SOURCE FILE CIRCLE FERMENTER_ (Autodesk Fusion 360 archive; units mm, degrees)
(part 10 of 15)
sketch "Schizzo3" plane through (-153.8, 0, 0) normal (-1, 0, 0) x axis (0, -1, 0)
  line L1 (78.45, -61) -> (81.95, -61)
  line L2 (10.25, -63.8607) -> (10.25, -61)
  line L3 (-10.25, -63.8607) -> (10.25, -63.8607)
  line L4 (-10.25, -61) -> (-10.25, -63.8607)
  line L5 (10.25, -61) -> (-10.25, -61)
  line L6 (-81.95, -61) -> (-78.45, -61)
  line L7 (-20, -52.5) -> (20, -52.5)
  line L8 (20, -27.5) -> (-20, -27.5)
  line L9 (83.1107, -5.4967) -> (83.1107, -63.5)
  line L10 (83.1107, 16.5) -> (83.1107, -1.5033)
  curve K1 (65, 34.6107) -> (83.1107, 16.5)
  line L11 (-65, 34.6107) -> (65, 34.6107)
  curve K2 (-83.1107, 16.5) -> (-65, 34.6107)
  line L12 (-83.1107, -1.5033) -> (-83.1107, 16.5)
  line L13 (-83.1107, -63.5) -> (-83.1107, -5.4967)
  curve K3 (-65, -81.6107) -> (-83.1107, -63.5)
  line L14 (65, -81.6107) -> (-65, -81.6107)
  curve K4 (83.1107, -63.5) -> (65, -81.6107)
  line L15 (0, -13.1465) -> (0, 0)
  line L16 (-83.1107, -21.5033) -> (-83.1107, -25.4967)
  line L17 (83.1107, -21.5033) -> (83.1107, -25.4967)
  curve K5 (83.1107, 20.6888) -> (83.1107, 16.5)
  curve K6 (83.0385, 23.5828) -> (83.1107, 20.6888)
  curve K7 (82.3781, 26.1138) -> (83.0385, 23.5828)
  curve K8 (82.0194, 27.4886) -> (82.3781, 26.1138)
  curve K9 (81.4495, 28.9265) -> (82.0194, 27.4886)
  curve K10 (80.4921, 30.2006) -> (81.4495, 28.9265)
  curve K11 (79.931, 30.9471) -> (80.4921, 30.2006)
  curve K12 (79.1144, 31.8115) -> (79.931, 30.9471)
  curve K13 (77.8234, 32.5796) -> (79.1144, 31.8115)
  curve K14 (76.3023, 33.4846) -> (77.8234, 32.5796)
  curve K15 (74.7016, 33.8962) -> (76.3023, 33.4846)
  curve K16 (73.5973, 34.1073) -> (74.7016, 33.8962)
  curve K17 (70.9971, 34.6043) -> (73.5973, 34.1073)
  curve K18 (67.9011, 34.6107) -> (70.9971, 34.6043)
  curve K19 (65, 34.6107) -> (67.9011, 34.6107)
  curve K20 (-68.2903, 34.6107) -> (-65, 34.6107)
  curve K21 (-71.7747, 34.5997) -> (-68.2903, 34.6107)
  curve K22 (-74.5519, 33.8966) -> (-71.7747, 34.5997)
  curve K23 (-76.1521, 33.4915) -> (-74.5519, 33.8966)
  curve K24 (-77.5147, 32.8746) -> (-76.1521, 33.4915)
  curve K25 (-78.6589, 32.0231) -> (-77.5147, 32.8746)
  curve K26 (-79.6443, 31.2898) -> (-78.6589, 32.0231)
  curve K27 (-80.4322, 30.4068) -> (-79.6443, 31.2898)
  curve K28 (-81.065, 29.3452) -> (-80.4322, 30.4068)
  curve K29 (-81.8269, 28.067) -> (-81.065, 29.3452)
  curve K30 (-82.3123, 26.6067) -> (-81.8269, 28.067)
  curve K31 (-82.6049, 25.1185) -> (-82.3123, 26.6067)
  curve K32 (-83.0566, 22.8211) -> (-82.6049, 25.1185)
  curve K33 (-83.1107, 20.1337) -> (-83.0566, 22.8211)
  curve K34 (-83.1107, 16.5) -> (-83.1107, 20.1337)
  curve K35 (-83.1107, -67.6888) -> (-83.1107, -63.5)
  curve K36 (-83.0385, -70.5828) -> (-83.1107, -67.6888)
  curve K37 (-82.3781, -73.1138) -> (-83.0385, -70.5828)
  curve K38 (-82.0194, -74.4886) -> (-82.3781, -73.1138)
  curve K39 (-81.4495, -75.9266) -> (-82.0194, -74.4886)
  curve K40 (-80.4921, -77.2006) -> (-81.4495, -75.9266)
  curve K41 (-79.931, -77.9471) -> (-80.4921, -77.2006)
  curve K42 (-79.1144, -78.8115) -> (-79.931, -77.9471)
  curve K43 (-77.8234, -79.5796) -> (-79.1144, -78.8115)
  curve K44 (-76.3023, -80.4846) -> (-77.8234, -79.5796)
  curve K45 (-74.7016, -80.8963) -> (-76.3023, -80.4846)
  curve K46 (-73.5973, -81.1073) -> (-74.7016, -80.8963)
  curve K47 (-70.9971, -81.6043) -> (-73.5973, -81.1073)
  curve K48 (-67.9011, -81.6107) -> (-70.9971, -81.6043)
  curve K49 (-65, -81.6107) -> (-67.9011, -81.6107)
  curve K50 (68.2903, -81.6107) -> (65, -81.6107)
  curve K51 (71.7747, -81.5997) -> (68.2903, -81.6107)
  curve K52 (74.5519, -80.8966) -> (71.7747, -81.5997)
  curve K53 (76.1521, -80.4915) -> (74.5519, -80.8966)
  curve K54 (77.5147, -79.8746) -> (76.1521, -80.4915)
  curve K55 (78.6589, -79.0231) -> (77.5147, -79.8746)
  curve K56 (79.6443, -78.2898) -> (78.6589, -79.0231)
  curve K57 (80.4322, -77.4068) -> (79.6443, -78.2898)
  curve K58 (81.065, -76.3452) -> (80.4322, -77.4068)
  curve K59 (81.8269, -75.067) -> (81.065, -76.3452)
  curve K60 (82.3123, -73.6067) -> (81.8269, -75.067)
  curve K61 (82.6049, -72.1185) -> (82.3123, -73.6067)
  curve K62 (83.0566, -69.8211) -> (82.6049, -72.1185)
  curve K63 (83.1107, -67.1337) -> (83.0566, -69.8211)
  curve K64 (83.1107, -63.5) -> (83.1107, -67.1337)
  line L18 (78.45, -61) -> (81.95, -61)
  line L19 (10.25, -63.8607) -> (10.25, -61)
  line L20 (-10.25, -63.8607) -> (10.25, -63.8607)
  line L21 (-10.25, -61) -> (-10.25, -63.8607)
  line L22 (-81.95, -61) -> (-78.45, -61)
  line L23 (-20, -52.5) -> (20, -52.5)
  line L24 (20, -27.5) -> (-20, -27.5)
  line L25 (83.1107, -5.4967) -> (83.1107, -63.5)
  line L26 (83.1107, 16.5) -> (83.1107, -1.5033)
  curve K65 (65, 34.6107) -> (83.1107, 16.5)
  line L27 (-65, 34.6107) -> (65, 34.6107)
  curve K66 (-83.1107, 16.5) -> (-65, 34.6107)
  line L28 (-83.1107, -1.5033) -> (-83.1107, 16.5)
  line L29 (-83.1107, -63.5) -> (-83.1107, -5.4967)
  curve K67 (-65, -81.6107) -> (-83.1107, -63.5)
  line L30 (65, -81.6107) -> (-65, -81.6107)
  curve K68 (83.1107, -63.5) -> (65, -81.6107)
  line L31 (10.25, -61) -> (-10.25, -61)
  arc A1 centre (80.2, -61) radius 1.75 clockwise from (78.45, -61) to (81.95, -61)
  arc A2 centre (-80.2, -61) radius 1.75 clockwise from (-81.95, -61) to (-78.45, -61)
  arc A3 centre (-20, -40) radius 12.5 clockwise from (-20, -52.5) to (-20, -27.5)
  arc A4 centre (20, -40) radius 12.5 clockwise from (20, -27.5) to (20, -52.5)
  circle C1 centre (44.1, 31.7) radius 1.75
  circle C2 centre (-44.1, 31.7) radius 1.75
  circle C3 centre (0, 31.7) radius 1.75
  arc A5 centre (82.6107, -5.4967) radius 0.5 clockwise from (82.3802, -5.053) to (83.1107, -5.4967)
  arc A6 centre (81.5735, -3.5) radius 1.75 clockwise from (82.3802, -5.053) to (82.3802, -1.947)
  arc A7 centre (82.6107, -1.5033) radius 0.5 clockwise from (83.1107, -1.5033) to (82.3802, -1.947)
  arc A8 centre (-82.6107, -1.5033) radius 0.5 clockwise from (-82.3802, -1.947) to (-83.1107, -1.5033)
  arc A9 centre (-81.5735, -3.5) radius 1.75 clockwise from (-82.3802, -1.947) to (-82.3802, -5.053)
  arc A10 centre (-82.6107, -5.4967) radius 0.5 clockwise from (-83.1107, -5.4967) to (-82.3802, -5.053)
  circle C4 centre (44.1, -78.7) radius 1.75
  circle C5 centre (-44.1, -78.7) radius 1.75
  circle C6 centre (0, -78.7) radius 1.75
  arc A11 centre (-82.6107, -25.4967) radius 0.5 clockwise from (-83.1107, -25.4967) to (-82.3802, -25.053)
  arc A12 centre (-81.5735, -23.5) radius 1.75 clockwise from (-82.3802, -21.947) to (-82.3802, -25.053)
  arc A13 centre (-82.6107, -21.5033) radius 0.5 clockwise from (-82.3802, -21.947) to (-83.1107, -21.5033)
  arc A14 centre (81.5735, -23.5) radius 1.75 clockwise from (82.3802, -25.053) to (82.3802, -21.947)
  arc A15 centre (82.6107, -21.5033) radius 0.5 clockwise from (83.1107, -21.5033) to (82.3802, -21.947)
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  point P1 (0, 0)
  point P54 (0, 0)
  point P46 (-82.3802, -25.053)
  point P57 (82.3802, -25.053)
  point P47 (-83.1107, -25.4967)
  point P63 (83.1107, -25.4967)
  point P49 (-82.3802, -21.947)
  point P59 (82.3802, -21.947)
  point P51 (-82.3802, -21.947)
  point P61 (82.3802, -21.947)
  point P52 (-83.1107, -21.5033)
  point P60 (83.1107, -21.5033)
  coincident P1 P54
  vertical L15
  tangent A11 L16
  symmetric P46 L15 P57
  symmetric P47 L15 P63
  symmetric P49 L15 P59
  symmetric A12 L15 A14
  symmetric P51 L15 P61
  symmetric P52 L15 P60
  symmetric A13 L15 A15
extrude "Estrusione5" add sketch "Schizzo3" profile of L1 A1 L2 L3 L4 L5 L6 A2 L7 A3 L8 A4 against normal blind 3
extrude "Estrusione6" cut sketch "Schizzo3" against normal blind 3
sketch "Schizzo4" plane through (-153.8, 0, 0) normal (-1, 0, 0) x axis (0, -1, 0)
  line L1 (-83.1107, -63.5) -> (-83.1107, -25.4967)
  curve K1 (-65, -81.6107) -> (-83.1107, -63.5)
  line L2 (65, -81.6107) -> (-65, -81.6107)
  curve K2 (83.1107, -63.5) -> (65, -81.6107)
  line L3 (83.1107, -25.4967) -> (83.1107, -63.5)
  line L4 (83.1107, -5.4967) -> (83.1107, -21.5033)
  line L5 (83.1107, 16.5) -> (83.1107, -1.5033)
  curve K3 (65, 34.6107) -> (83.1107, 16.5)
  line L6 (-65, 34.6107) -> (65, 34.6107)
  curve K4 (-83.1107, 16.5) -> (-65, 34.6107)
  line L7 (-83.1107, -1.5033) -> (-83.1107, 16.5)
  line L8 (-83.1107, -21.5033) -> (-83.1107, -5.4967)
  line L9 (-83.1107, -1.5033) -> (-83.1107, -5.4967)
  line L10 (83.1107, -5.4967) -> (83.1107, -1.5033)
  arc A1 centre (-82.6107, -25.4967) radius 0.5 clockwise from (-83.1107, -25.4967) to (-82.3802, -25.053)
  arc A2 centre (82.6107, -25.4967) radius 0.5 clockwise from (82.3802, -25.053) to (83.1107, -25.4967)
  arc A3 centre (81.5735, -23.5) radius 1.75 clockwise from (82.3802, -25.053) to (82.3802, -21.947)
  arc A4 centre (82.6107, -21.5033) radius 0.5 clockwise from (83.1107, -21.5033) to (82.3802, -21.947)
  arc A5 centre (82.6107, -5.4967) radius 0.5 clockwise from (82.3802, -5.053) to (83.1107, -5.4967)
  arc A6 centre (81.5735, -3.5) radius 1.75 clockwise from (82.3802, -5.053) to (82.3802, -1.947)
  arc A7 centre (82.6107, -1.5033) radius 0.5 clockwise from (83.1107, -1.5033) to (82.3802, -1.947)
  arc A8 centre (-82.6107, -1.5033) radius 0.5 clockwise from (-82.3802, -1.947) to (-83.1107, -1.5033)
  arc A9 centre (-81.5735, -3.5) radius 1.75 clockwise from (-82.3802, -1.947) to (-82.3802, -5.053)
  arc A10 centre (-82.6107, -5.4967) radius 0.5 clockwise from (-83.1107, -5.4967) to (-82.3802, -5.053)
  arc A11 centre (-82.6107, -21.5033) radius 0.5 clockwise from (-82.3802, -21.947) to (-83.1107, -21.5033)
  arc A12 centre (-81.5735, -23.5) radius 1.75 clockwise from (-82.3802, -21.947) to (-82.3802, -25.053)
  circle C1 centre (-44.1, 31.7) radius 1.75
  circle C2 centre (-44.1, -78.7) radius 1.75
  circle C3 centre (44.1, 31.7) radius 1.75
  circle C4 centre (0, 31.7) radius 1.75
  circle C5 centre (44.1, -78.7) radius 1.75
  circle C6 centre (0, -78.7) radius 1.75
  point P32 (-83.1107, -5.4967)
  point P40 (-83.1107, -5.4967)
  point P27 (-83.1107, -1.5033)
  point P41 (-83.1107, -1.5033)
  point P21 (83.1107, -1.5033)
  point P42 (83.1107, -1.5033)
  point P16 (83.1107, -5.4967)
  point P43 (83.1107, -5.4967)
  coincident P32 P40
  coincident P27 P41
  coincident P21 P42
  coincident P16 P43
extrude "Estrusione7" add sketch "Schizzo4" profile of A5 A6 A7 A8 A9 A10 L9 L10 against normal blind 3
sketch "Schizzo5" plane through (-153.8, 0, 0) normal (-1, 0, 0) x axis (0, -1, 0)
  line L1 (-83.1107, -63.5) -> (-83.1107, -25.4967)
  curve K1 (-65, -81.6107) -> (-83.1107, -63.5)
  line L2 (65, -81.6107) -> (-65, -81.6107)
  curve K2 (83.1107, -63.5) -> (65, -81.6107)
  line L3 (83.1107, -25.4967) -> (83.1107, -63.5)
  line L4 (83.1107, 16.5) -> (83.1107, -21.5033)
  curve K3 (65, 34.6107) -> (83.1107, 16.5)
  line L5 (-65, 34.6107) -> (65, 34.6107)
  curve K4 (-83.1107, 16.5) -> (-65, 34.6107)
  line L6 (-83.1107, -21.5033) -> (-83.1107, 16.5)
  line L7 (-79.8235, -23.5) -> (79.8235, -23.5)
  arc A1 centre (-82.6107, -25.4967) radius 0.5 clockwise from (-83.1107, -25.4967) to (-82.3802, -25.053)
  arc A2 centre (82.6107, -25.4967) radius 0.5 clockwise from (82.3802, -25.053) to (83.1107, -25.4967)
  arc A3 centre (81.5735, -23.5) radius 1.75 clockwise from (82.3802, -25.053) to (82.3802, -21.947)
  arc A4 centre (82.6107, -21.5033) radius 0.5 clockwise from (83.1107, -21.5033) to (82.3802, -21.947)
  arc A5 centre (-82.6107, -21.5033) radius 0.5 clockwise from (-82.3802, -21.947) to (-83.1107, -21.5033)
  arc A6 centre (-81.5735, -23.5) radius 1.75 clockwise from (-82.3802, -21.947) to (-82.3802, -25.053)
  circle C1 centre (-44.1, 31.7) radius 1.75
  circle C2 centre (-44.1, -78.7) radius 1.75
  circle C3 centre (44.1, 31.7) radius 1.75
  circle C4 centre (0, 31.7) radius 1.75
  circle C5 centre (44.1, -78.7) radius 1.75
  circle C6 centre (0, -78.7) radius 1.75
  point P26 (79.8235, -23.5)
  point P27 (-79.8235, -23.5)
  point P28 (0, -23.5)
  midpoint A3 P26
  midpoint A6 P27
  midpoint L7 P28
component_insert "Inserimento componente3"
joint "Assembla5" alignAngle 0 alignOffsetX 0 alignOffsetY 0 alignOffsetZ 0
sketch "Schizzo10" plane through (-153.8, 0, 0) normal (-1, 0, 0) x axis (0, -1, 0)
  line L1 (-83.1107, -63.5) -> (-83.1107, -25.4967)
  curve K1 (-65, -81.6107) -> (-83.1107, -63.5)
  line L2 (65, -81.6107) -> (-65, -81.6107)
  curve K2 (83.1107, -63.5) -> (65, -81.6107)
  line L3 (83.1107, -25.4967) -> (83.1107, -63.5)
  line L4 (83.1107, 16.5) -> (83.1107, -21.5033)
  curve K3 (65, 34.6107) -> (83.1107, 16.5)
  line L5 (-65, 34.6107) -> (65, 34.6107)
  curve K4 (-83.1107, 16.5) -> (-65, 34.6107)
  line L6 (-83.1107, -21.5033) -> (-83.1107, 16.5)
  arc A1 centre (-82.6107, -25.4967) radius 0.5 clockwise from (-83.1107, -25.4967) to (-82.3802, -25.053)
  arc A2 centre (82.6107, -25.4967) radius 0.5 clockwise from (82.3802, -25.053) to (83.1107, -25.4967)
  arc A3 centre (81.5735, -23.5) radius 1.75 clockwise from (82.3802, -25.053) to (82.3802, -21.947)
  arc A4 centre (82.6107, -21.5033) radius 0.5 clockwise from (83.1107, -21.5033) to (82.3802, -21.947)
  arc A5 centre (-82.6107, -21.5033) radius 0.5 clockwise from (-82.3802, -21.947) to (-83.1107, -21.5033)
  arc A6 centre (-81.5735, -23.5) radius 1.75 clockwise from (-82.3802, -21.947) to (-82.3802, -25.053)
  circle C1 centre (-44.1, 31.7) radius 1.75
  circle C2 centre (-44.1, -78.7) radius 1.75
  circle C3 centre (-23, -23.5) radius 19.5
  arc A7 centre (21, -23.5) radius 12.5 clockwise from (10.7587, -30.667) to (10.7587, -16.3331)
  circle C4 centre (21, -23.5) radius 12.5
  circle C5 centre (44.1, 31.7) radius 1.75
  circle C6 centre (0, 31.7) radius 1.75
  circle C7 centre (44.1, -78.7) radius 1.75
  circle C8 centre (0, -78.7) radius 1.75
  concentric A7 C4
extrude "Estrusione8" cut sketch "Schizzo10" profile of C3 A7 C4 against normal blind 3
sketch "Schizzo6" plane through (-153.8, 0, 0) normal (-1, 0, 0) x axis (0, -1, 0)
  line L1 (-83.1107, -63.5) -> (-83.1107, -25.4967)
  curve K1 (-65, -81.6107) -> (-83.1107, -63.5)
  line L2 (65, -81.6107) -> (-65, -81.6107)
  curve K2 (83.1107, -63.5) -> (65, -81.6107)
  line L3 (83.1107, -25.4967) -> (83.1107, -63.5)
  line L4 (83.1107, 16.5) -> (83.1107, -21.5033)
  curve K3 (65, 34.6107) -> (83.1107, 16.5)
  line L5 (-65, 34.6107) -> (65, 34.6107)
  curve K4 (-83.1107, 16.5) -> (-65, 34.6107)
  line L6 (-83.1107, -21.5033) -> (-83.1107, 16.5)
  curve K5 (27.4022, -27.4066) -> (27.5488, -28.6346)
  line L7 (29.7149, -30.8007) -> (27.5488, -28.6346)
  curve K6 (29.7149, -30.8007) -> (31.2413, -30.667)
  curve K7 (31.2413, -16.3331) -> (29.7149, -16.1993)
  line L8 (27.5488, -18.3654) -> (29.7149, -16.1993)
  curve K8 (27.5488, -18.3654) -> (27.4022, -19.5934)
  curve K9 (10.7587, -30.667) -> (12.2851, -30.8007)
  line L9 (14.4512, -28.6346) -> (12.2851, -30.8007)
  curve K10 (14.4512, -28.6346) -> (14.5978, -27.4066)
  curve K11 (14.5978, -19.5934) -> (14.4512, -18.3654)
  line L10 (12.2851, -16.1993) -> (14.4512, -18.3654)
  curve K12 (12.2851, -16.1993) -> (10.7587, -16.3331)
  line L11 (45.4, -39.9) -> (45.4, -7.1)
  line L12 (-39.4, -45.9) -> (39.4, -45.9)
  line L13 (-45.4, -7.1) -> (-45.4, -39.9)
  line L14 (39.4, -1.1) -> (-39.4, -1.1)
  curve K13 (15.8654, -16.9512) -> (17.0934, -17.0978)
  curve K14 (24.9066, -17.0978) -> (26.1346, -16.9512)
  line L15 (28.3007, -14.7851) -> (26.1346, -16.9512)
  curve K15 (28.3007, -14.7851) -> (28.167, -13.2587)
  curve K16 (13.833, -13.2587) -> (13.6993, -14.7851)
  line L16 (15.8654, -16.9512) -> (13.6993, -14.7851)
  curve K17 (28.167, -33.7413) -> (28.3007, -32.2149)
  line L17 (26.1346, -30.0488) -> (28.3007, -32.2149)
  curve K18 (26.1346, -30.0488) -> (24.9066, -29.9022)
  curve K19 (17.0934, -29.9022) -> (15.8654, -30.0488)
  line L18 (13.6993, -32.2149) -> (15.8654, -30.0488)
  curve K20 (13.6993, -32.2149) -> (13.833, -33.7413)
  circle C1 centre (21, -23.5) radius 12.5
  circle C2 centre (-23, -23.5) radius 19.5
  arc A1 centre (-82.6107, -25.4967) radius 0.5 clockwise from (-83.1107, -25.4967) to (-82.3802, -25.053)
  arc A2 centre (82.6107, -25.4967) radius 0.5 clockwise from (82.3802, -25.053) to (83.1107, -25.4967)
  arc A3 centre (81.5735, -23.5) radius 1.75 clockwise from (82.3802, -25.053) to (82.3802, -21.947)
  arc A4 centre (82.6107, -21.5033) radius 0.5 clockwise from (83.1107, -21.5033) to (82.3802, -21.947)
  arc A5 centre (-82.6107, -21.5033) radius 0.5 clockwise from (-82.3802, -21.947) to (-83.1107, -21.5033)
  arc A6 centre (-81.5735, -23.5) radius 1.75 clockwise from (-82.3802, -21.947) to (-82.3802, -25.053)
  circle C3 centre (-44.1, 31.7) radius 1.75
  circle C4 centre (-44.1, -78.7) radius 1.75
  circle C5 centre (-39, -7.5) radius 1.725
  arc A7 centre (21, -23.5) radius 7.5 clockwise from (27.4022, -19.5934) to (27.4022, -27.4066)
  arc A8 centre (21, -23.5) radius 12.5 clockwise from (31.2413, -16.3331) to (31.2413, -30.667)
  arc A9 centre (21, -23.5) radius 12.5 clockwise from (10.7587, -30.667) to (10.7587, -16.3331)
  arc A10 centre (21, -23.5) radius 7.5 clockwise from (14.5978, -27.4066) to (14.5978, -19.5934)
  circle C6 centre (21, -23.5) radius 5.5
  arc A11 centre (39.4, -39.9) radius 6 clockwise from (45.4, -39.9) to (39.4, -45.9)
  arc A12 centre (-39.4, -39.9) radius 6 clockwise from (-39.4, -45.9) to (-45.4, -39.9)
  arc A13 centre (-39.4, -7.1) radius 6 clockwise from (-45.4, -7.1) to (-39.4, -1.1)
  arc A14 centre (39.4, -7.1) radius 6 clockwise from (39.4, -1.1) to (45.4, -7.1)
  circle C7 centre (-39, -7.5) radius 1.725
  arc A15 centre (21, -23.5) radius 7.5 clockwise from (17.0934, -17.0978) to (24.9066, -17.0978)
  arc A16 centre (21, -23.5) radius 12.5 clockwise from (13.833, -13.2587) to (28.167, -13.2587)
  circle C8 centre (39, -7.5) radius 1.875
  circle C9 centre (-39, -39.5) radius 1.725
  circle C10 centre (-23, -23.5) radius 19.5
  arc A17 centre (21, -23.5) radius 12.5 clockwise from (28.167, -33.7413) to (13.833, -33.7413)
  arc A18 centre (21, -23.5) radius 7.5 clockwise from (24.9066, -29.9022) to (17.0934, -29.9022)
  circle C11 centre (39, -39.5) radius 1.875
  circle C12 centre (44.1, 31.7) radius 1.75
  circle C13 centre (0, 31.7) radius 1.75
  circle C14 centre (44.1, -78.7) radius 1.75
  circle C15 centre (0, -78.7) radius 1.75
extrude "Estrusione9" cut sketch "Schizzo6" profile of C5 C7 C8 C9 C11 against normal blind 3
sketch "Schizzo7" plane through (-153.8, 0, 0) normal (-1, 0, 0) x axis (0, -1, 0)
  line L1 (-83.1107, -63.5) -> (-83.1107, -25.4967)
  curve K1 (-65, -81.6107) -> (-83.1107, -63.5)
  line L2 (65, -81.6107) -> (-65, -81.6107)
  curve K2 (83.1107, -63.5) -> (65, -81.6107)
  line L3 (83.1107, -25.4967) -> (83.1107, -63.5)
  line L4 (83.1107, 16.5) -> (83.1107, -21.5033)
  curve K3 (65, 34.6107) -> (83.1107, 16.5)
  line L5 (-65, 34.6107) -> (65, 34.6107)
  curve K4 (-83.1107, 16.5) -> (-65, 34.6107)
  line L6 (-83.1107, -21.5033) -> (-83.1107, 16.5)
  line L7 (-10, -63.3618) -> (-10, -59.8857)
  line L8
  line L9 (-10, -49.8981) -> (-10, -63.3232)
  line L10 (-10, -49.8981) -> (-10, -49.8595)
  line L11 (-10, -53.3357) -> (-10, -49.8595)
  line L12 (-10, -54.6457) -> (-10, -53.3357)
  line L13 (-10, -55.9557) -> (-10, -54.6457)
  line L14 (-10, -57.2657) -> (-10, -55.9557)
  line L15 (-10, -58.5757) -> (-10, -57.2657)
  line L16 (-10, -59.8857) -> (-10, -58.5757)
  line L17 (0.01, -63.6118) -> (-1.3, -63.6118)
  line L18 (1.32, -63.6118) -> (0.01, -63.6118)
  line L19 (2.63, -63.6118) -> (1.32, -63.6118)
  line L20 (3.94, -63.6118) -> (2.63, -63.6118)
  line L21 (5.25, -63.6118) -> (3.94, -63.6118)
  line L22 (9.75, -63.6118) -> (5.25, -63.6118)
  line L23 (-10, -63.6118) -> (9.75, -63.6118)
  line L24 (-10, -63.6118) -> (-9.75, -63.6118)
  line L25 (-6.54, -63.6118) -> (-9.75, -63.6118)
  line L26 (-5.23, -63.6118) -> (-6.54, -63.6118)
  line L27 (-3.92, -63.6118) -> (-5.23, -63.6118)
  line L28 (-2.61, -63.6118) -> (-3.92, -63.6118)
  line L29 (-1.3, -63.6118) -> (-2.61, -63.6118)
  line L30 (10.25, -63.8618) -> (-10.25, -63.8618)
  line L31 (10.25, -49.3618) -> (10.25, -63.8618)
  line L32 (-10.25, -49.3618) -> (10.25, -49.3618)
  line L33 (-10.25, -63.8618) -> (-10.25, -49.3618)
  circle C1 centre (39, -39.5) radius 1.875
  circle C2 centre (-39, -39.5) radius 1.725
  circle C3 centre (39, -7.5) radius 1.875
  circle C4 centre (-39, -7.5) radius 1.725
  circle C5 centre (21, -23.5) radius 12.5
  circle C6 centre (-23, -23.5) radius 19.5
  arc A1 centre (-82.6107, -25.4967) radius 0.5 clockwise from (-83.1107, -25.4967) to (-82.3802, -25.053)
  arc A2 centre (82.6107, -25.4967) radius 0.5 clockwise from (82.3802, -25.053) to (83.1107, -25.4967)
  arc A3 centre (81.5735, -23.5) radius 1.75 clockwise from (82.3802, -25.053) to (82.3802, -21.947)
  arc A4 centre (82.6107, -21.5033) radius 0.5 clockwise from (83.1107, -21.5033) to (82.3802, -21.947)
  arc A5 centre (-82.6107, -21.5033) radius 0.5 clockwise from (-82.3802, -21.947) to (-83.1107, -21.5033)
  arc A6 centre (-81.5735, -23.5) radius 1.75 clockwise from (-82.3802, -21.947) to (-82.3802, -25.053)
  circle C7 centre (-44.1, 31.7) radius 1.75
  circle C8 centre (-44.1, -78.7) radius 1.75
  circle C9 centre (-12.35, -56.6107) radius 1.55
  circle C10 centre (44.1, 31.7) radius 1.75
  circle C11 centre (0, 31.7) radius 1.75
  circle C12 centre (44.1, -78.7) radius 1.75
  circle C13 centre (0, -78.7) radius 1.75
  horizontal L30
  vertical L31
  horizontal L32
  vertical L33
  dimension "d1351" distance L11 L33 = 0.25
  dimension "d1352" distance L25 L30 = 0.25
  dimension "d1353" distance L31 L33 = 20.5
  dimension "d1354" distance L30 L32 = 14.5
extrude "Estrusione10" cut sketch "Schizzo7" profile of L30 L31 L32 L33 C9 against normal blind 3
work_plane "Piano di lavoro3"
split "Dividi1"
remove_body "RimuoviCorpo1"
extrude "Estrusione9" cut of existing geometry blind -37.5
work_plane "Piano di lavoro4" AlongDistance -20
split "Dividi2"
move "Sposta1"
work_plane "Piano di lavoro5" AlongDistance -25
split "Dividi3"
remove_body "RimuoviCorpo2"
remove_body "RimuoviCorpo3"
mirror "Specchio2" mirrorStitchTolerance 0.1
remove_body "RimuoviCorpo4"
remove_body "RimuoviCorpo5"
extrude "Estrusione10" add of existing geometry blind 20
sketch "Schizzo10" plane through (-180, 0, 0) normal (-1, 0, 0) x axis (0, -1, 0)
  line L1 (81.4, -63.5) -> (81.4, -43.5)
  curve K1 (81.4, -63.5) -> (65, -79.9)
  line L2 (-65, -79.9) -> (65, -79.9)
  curve K2 (-65, -79.9) -> (-81.4, -63.5)
  line L3 (-81.4, -43.5) -> (-81.4, -63.5)
  line L4 (-90, -63.5) -> (-90, -43.5)
  curve K3 (-65, -88.5) -> (-90, -63.5)
  line L5 (65, -88.5) -> (-65, -88.5)
  curve K4 (90, -63.5) -> (65, -88.5)
  line L6 (90, -43.5) -> (90, -63.5)
  line L7 (0, -79.9) -> (0, -88.5)
  line L8 (-90, -43.5) -> (-81.4, -43.5)
  line L9 (81.4, -43.5) -> (90, -43.5)
  circle C1 centre (25, -82.9) radius 1.75
  circle C2 centre (25, -82.9) radius 1.75
  circle C3 centre (-25, -82.9) radius 1.75
  point P15 (0, -88.5)
  point P16 (0, -79.9)
  midpoint L5 P15
  midpoint L2 P16
  symmetric L7 C2 C3
extrude "Estrusione11" cut sketch "Schizzo10" profile of C3 against normal blind 13.074
sketch "Schizzo11" plane through (-153.8, -0.1327, -0.0276) normal (1, 0, 0) x axis (0, 1, 0)
  curve K1 (-43.0092, -79.4977) -> (-43.5688, -77.1818)
  curve K2 (-44.3658, -77.1818) -> (-44.9254, -79.4977)
  line L1 (-84.8181, -63.4724) -> (-84.8181, -43.4724)
  curve K3 (-64.8673, -83.4232) -> (-84.8181, -63.4724)
  line L2 (65.1327, -83.4232) -> (-64.8673, -83.4232)
  curve K4 (85.0834, -63.4724) -> (65.1327, -83.4232)
  line L3 (85.0834, -43.4724) -> (85.0834, -63.4724)
  line L4 (77.3834, -63.4724) -> (77.3834, -43.4724)
  curve K5 (77.3834, -63.4724) -> (65.1327, -75.7232)
  line L5 (-64.8673, -75.7232) -> (65.1327, -75.7232)
  curve K6 (-64.8673, -75.7232) -> (-77.1181, -63.4724)
  line L6 (-77.1181, -43.4724) -> (-77.1181, -63.4724)
  line L7 (77.3834, -43.4724) -> (85.0834, -43.4724)
  line L8 (-84.8181, -43.4724) -> (-77.1181, -43.4724)
  arc A1 centre (-43.9673, -78.6724) radius 1.2645 clockwise from (-43.0092, -79.4977) to (-44.9254, -79.4977)
  arc A2 centre (-43.9673, -78.6724) radius 1.543 clockwise from (-44.3658, -77.1818) to (-43.5688, -77.1818)
  circle C1 centre (0.1327, -78.6724) radius 1.75
  circle C2 centre (44.2327, -78.6724) radius 1.75
extrude "Estrusione12" cut sketch "Schizzo11" profile of C1 C2 against normal blind 3
thread "Filettatura2"
combine "Combina1"
mirror "Specchio3" mirrorStitchTolerance 0.1
work_plane "Piano di lavoro1"
split "Dividi1"
remove_body "RimuoviCorpo1"
extrude "Estrusione3" cut of existing geometry blind -37.5
work_plane "Piano di lavoro2" AlongDistance -40
split "Dividi2"
move "Sposta1"
extrude "Estrusione4" add of existing geometry blind 20
work_plane "Piano di lavoro3" AlongDistance -20
split "Dividi3"
remove_body "RimuoviCorpo2"
mirror "Specchio2" mirrorStitchTolerance 0.1
sketch "Schizzo5" plane through (-183, 0, 0) normal (-1, 0, 0) x axis (0, -1, 0)
  line L1 (-86.5355, -32.7047) -> (-79.4522, -25.6213)
  line L2 (-88, -63.5) -> (-88, -36.2402)
  curve K1 (-88, -63.5) -> (-65, -86.5)
  line L3 (65, -86.5) -> (-65, -86.5)
  curve K2 (88, -63.5) -> (65, -86.5)
  line L4 (88, -36.2402) -> (88, -63.5)
  line L5 (79.4522, -25.6213) -> (86.5355, -32.7047)
  line L6 (86.5355, -14.2954) -> (79.4522, -21.3787)
  line L7 (88, 16.5) -> (88, -10.7598)
  curve K3 (88, 16.5) -> (65, 39.5)
  line L8 (-65, 39.5) -> (65, 39.5)
  curve K4 (-88, 16.5) -> (-65, 39.5)
  line L9 (-88, -10.7598) -> (-88, 16.5)
  line L10 (-79.4522, -21.3787) -> (-86.5355, -14.2954)
  line L11 (45.4, -7.1) -> (45.4, -39.9)
  line L12 (-39.4, -1.1) -> (39.4, -1.1)
  line L13 (-45.4, -39.9) -> (-45.4, -7.1)
  line L14 (39.4, -45.9) -> (-39.4, -45.9)
  line L15 (-39.4, -0.6) -> (39.4, -0.6)
  line L16 (-45.9, -39.9) -> (-45.9, -7.1)
  line L17 (39.4, -46.4) -> (-39.4, -46.4)
  line L18 (45.9, -7.1) -> (45.9, -39.9)
  circle C1 centre (-25, 35.9) radius 1.75
  circle C2 centre (25, 35.9) radius 1.75
  circle C3 centre (0, -17) radius 1.75
  circle C4 centre (0, -30) radius 1.75
  arc A1 centre (-81.5735, -23.5) radius 3 clockwise from (-79.4522, -21.3787) to (-79.4522, -25.6213)
  arc A2 centre (-83, -36.2402) radius 5 clockwise from (-88, -36.2402) to (-86.5355, -32.7047)
  arc A3 centre (83, -36.2402) radius 5 clockwise from (86.5355, -32.7047) to (88, -36.2402)
  arc A4 centre (81.5735, -23.5) radius 3 clockwise from (79.4522, -25.6213) to (79.4522, -21.3787)
  arc A5 centre (83, -10.7598) radius 5 clockwise from (88, -10.7598) to (86.5355, -14.2954)
  arc A6 centre (-83, -10.7598) radius 5 clockwise from (-86.5355, -14.2954) to (-88, -10.7598)
  circle C5 centre (25, -82.9) radius 1.75
  circle C6 centre (-25, -82.9) radius 1.75
  arc A7 centre (39.4, -7.1) radius 6 clockwise from (39.4, -1.1) to (45.4, -7.1)
  arc A8 centre (-39.4, -7.1) radius 6 clockwise from (-45.4, -7.1) to (-39.4, -1.1)
  arc A9 centre (-39.4, -39.9) radius 6 clockwise from (-39.4, -45.9) to (-45.4, -39.9)
  arc A10 centre (39.4, -39.9) radius 6 clockwise from (45.4, -39.9) to (39.4, -45.9)
  arc A11 centre (-39.4, -7.1) radius 6.5 clockwise from (-45.9, -7.1) to (-39.4, -0.6)
  arc A12 centre (-39.4, -39.9) radius 6.5 clockwise from (-39.4, -46.4) to (-45.9, -39.9)
  arc A13 centre (39.4, -39.9) radius 6.5 clockwise from (45.9, -39.9) to (39.4, -46.4)
  arc A14 centre (39.4, -7.1) radius 6.5 clockwise from (39.4, -0.6) to (45.9, -7.1)
  dimension "d1379" = 0.5
extrude "Estrusione5" cut sketch "Schizzo5" profile of C3 C4 L11 A7 L12 A8 L13 A9 L14 A10 A14 A12 L15 A11 A13 L17 L16 L18 against normal blind 3
sketch "Schizzo1" plane through (180, 0, 0) normal (1, 0, 0) x axis (0, 1, 0)
  line L1 (88.4, -63.5) -> (88.4, 91.5)
  curve K1 (65, -86.9) -> (88.4, -63.5)
  line L2 (-65, -86.9) -> (65, -86.9)
  curve K2 (-65, -86.9) -> (-88.4, -63.5)
  line L3 (-88.4, 91.5) -> (-88.4, -63.5)
  curve K3 (-65, 114.9) -> (-88.4, 91.5)
  line L4 (65, 114.9) -> (-65, 114.9)
  curve K4 (65, 114.9) -> (88.4, 91.5)
  line L5 (90, 91.5) -> (90, -63.5)
  curve K5 (65, 116.5) -> (90, 91.5)
  line L6 (-65, 116.5) -> (65, 116.5)
  curve K6 (-65, 116.5) -> (-90, 91.5)
  line L7 (-90, -63.5) -> (-90, 91.5)
  curve K7 (-65, -88.5) -> (-90, -63.5)
  line L8 (65, -88.5) -> (-65, -88.5)
  curve K8 (65, -88.5) -> (90, -63.5)
  line L9 (65, 116.5) -> (-65, 116.5)
  line L10 (65, 129.9) -> (-65, 129.9)
  curve K9 (-65, 116.5) -> (-90, 91.5)
  curve K10 (65, 116.5) -> (90, 91.5)
  line L11 (-65, 123.2) -> (65, 123.2)
  line L12 (0, 129.9) -> (0, 116.5)
  curve K11 (-65, 129.9) -> (-90, 154.9)
  curve K12 (65, 129.9) -> (90, 154.9)
  line L13 (90, 159.9) -> (90, 154.9)
  line L14 (-90, 159.9) -> (-90, 154.9)
  line L15 (-90, 159.9) -> (90, 159.9)
  curve K13 (-65, 189.9) -> (-90, 164.9)
  line L16 (-90, 159.9) -> (-90, 164.9)
  line L17 (65, 189.9) -> (-65, 189.9)
  curve K14 (65, 189.9) -> (90, 164.9)
  line L18 (90, 159.9) -> (90, 164.9)
  point P26 (0, 116.5)
  point P27 (0, 129.9)
  point P18 (-65, 116.5)
  point P29 (-65, 129.9)
  point P19 (65, 116.5)
  point P31 (65, 129.9)
  point P22 (-90, 91.5)
  point P28 (-90, 154.9)
  point P23 (90, 91.5)
  point P30 (90, 154.9)
  point P20 (-65, 129.9)
  point P37 (-65, 189.9)
  point P21 (65, 129.9)
  point P38 (65, 189.9)
  point P34 (-90, 164.9)
  point P35 (-65, 189.9)
  point P39 (90, 164.9)
  point P40 (65, 189.9)
  point P32 (90, 159.9)
  point P41 (90, 159.9)
  point P33 (-90, 159.9)
  point P36 (-90, 159.9)
  parallel L10 L11
  midpoint L6 P26
  midpoint L10 P27
  perpendicular L10 L12
  midpoint L11 L12
  symmetric P18 L11 P29
  symmetric P19 L11 P31
  symmetric P22 L11 P28
  symmetric K9 L11 K11
  symmetric P23 L11 P30
  symmetric K10 L11 K12
  vertical L13
  vertical L14
  perpendicular L14 L15
  symmetric P20 L15 P37
  symmetric P21 L15 P38
  symmetric P28 L15 P34
  symmetric P29 L15 P35
  symmetric K11 L15 K13
  symmetric P30 L15 P39
  symmetric P31 L15 P40
  symmetric K12 L15 K14
  symmetric P32 L15 P41
  symmetric P33 L15 P36
  dimension "d1382" = -13.4
  dimension "d1384" distance P30 P32 = 5
  dimension "d1385" distance P28 P33 = 5
extrude "Estrusione1" new body sketch "Schizzo1" profile of L10 K11 K12 L13 L14 K13 L16 L17 K14 L18 against normal blind 360
extrude "Estrusione2" cut of existing geometry blind -340
shell "Svuotamento1" innerThickness 1.6
extrude "Estrusione3" cut of existing geometry blind -106.959
work_plane "Piano di lavoro1"
split "Dividi1"
remove_body "RimuoviCorpo1"
sketch "Schizzo2" plane through (0, 0, 159.9) normal (0, 0, 1) x axis (-1, 0, 0)
  line L1 (-160, 88.4) -> (-180, 88.4)
  line L2 (-160, 90) -> (-160, 88.4)
  line L3 (-180, 90) -> (-160, 90)
  line L4 (-180, 88.4) -> (-180, 90)
  line L5 (-180, 77.9) -> (-180, 90)
  line L6 (-170, 77.9) -> (-180, 77.9)
  curve K1 (-177, 88.4) -> (-180, 88.4)
  curve K2 (-175, 83.15) -> (-177, 88.4)
  curve K3 (-173, 77.9) -> (-175, 83.15)
  curve K4 (-170, 77.9) -> (-173, 77.9)
  curve K5 (-170, 77.9) -> (-180, 88.4)
  line L7 (-170, 88.4) -> (-170, 77.9)
  point P5 (-180, 90)
  point P6 (-180, 90)
  point P9 (-177, 88.4)
  point P11 (-173, 77.9)
  point P12 (-170, 88.4)
  point P7 (-180, 77.9)
  point P8 (-170, 77.9)
  point P2 (-180, 88.4)
  coincident P5 P6
  perpendicular L3 L5
  perpendicular L5 L6
  coincident L1 P9
  coincident L6 P11
  equal K2 K3
  coincident L1 P12
  perpendicular L1 L7
  parallel K2 K3
  dimension "d1393" distance P6 P7 = 12.1
  dimension "d1394" distance P7 P8 = 10
  dimension "d1395" distance P2 P9 = 3
  dimension "d1396" distance P8 P11 = 3
sweep "Sweep1" sketch "Schizzo2" TwistAngle 0 TaperAngle 0
chamfer "Smusso1" distance 0.8
mirror "Specchio1" mirrorStitchTolerance 0.1
sketch "Schizzo1" plane through (170, 0, 0) normal (-1, 0, 0) x axis (0, -1, 0)
  line L1 (-88.4, 154.9) -> (-88.4, 164.9)
  curve K1 (-88.4, 154.9) -> (-65, 131.5)
  line L2 (65, 131.5) -> (-65, 131.5)
  curve K2 (65, 131.5) -> (88.4, 154.9)
  line L3 (88.4, 164.9) -> (88.4, 154.9)
  curve K3 (65, 188.3) -> (88.4, 164.9)
  line L4 (-65, 188.3) -> (65, 188.3)
  curve K4 (-88.4, 164.9) -> (-65, 188.3)
  line L5 (-77.9, 164.9) -> (-77.9, 154.9)
  curve K5 (-77.9, 164.9) -> (-65, 177.8)
  line L6 (65, 177.8) -> (-65, 177.8)
  curve K6 (65, 177.8) -> (77.9, 164.9)
  line L7 (77.9, 154.9) -> (77.9, 164.9)
  curve K7 (65, 142) -> (77.9, 154.9)
  line L8 (-65, 142) -> (65, 142)
  curve K8 (-77.9, 154.9) -> (-65, 142)
  line L9 (-65, 142) -> (65, 142)
  curve K9 (65, 142) -> (77.9, 154.9)
  line L10 (77.9, 164.9) -> (77.9, 154.9)
  curve K10 (65, 177.8) -> (77.9, 164.9)
  line L11 (-65, 177.8) -> (65, 177.8)
  curve K11 (-77.9, 164.9) -> (-65, 177.8)
  line L12 (-77.9, 164.9) -> (-77.9, 154.9)
  curve K12 (-77.9, 154.9) -> (-65, 142)
  line L13 (-85.9, 164.9) -> (-85.9, 154.9)
  curve K13 (-85.9, 164.9) -> (-65, 185.8)
  line L14 (-65, 185.8) -> (65, 185.8)
  curve K14 (65, 185.8) -> (85.9, 164.9)
  line L15 (85.9, 164.9) -> (85.9, 154.9)
  curve K15 (65, 134) -> (85.9, 154.9)
  line L16 (-65, 134) -> (65, 134)
  curve K16 (-85.9, 154.9) -> (-65, 134)
  dimension "d1410" = 8
extrude "Estrusione1" new body sketch "Schizzo1" profile of L5 K5 L6 K6 L7 K7 L8 K8 L9 K9 L10 K10 L11 K11 L12 K12 L15 L13 K13 L14 K16 K14 K15 L16 along normal blind 3
component_from_bodies "Corpo->Comp1"
sketch "Schizzo1" plane through (170, 0, 0) normal (-1, 0, 0) x axis (0, -1, 0)
  line L1 (-88.4, 154.9) -> (-88.4, 164.9)
  curve K1 (-88.4, 154.9) -> (-65, 131.5)
  line L2 (65, 131.5) -> (-65, 131.5)
  curve K2 (65, 131.5) -> (88.4, 154.9)
  line L3 (88.4, 164.9) -> (88.4, 154.9)
  curve K3 (65, 188.3) -> (88.4, 164.9)
  line L4 (-65, 188.3) -> (65, 188.3)
  curve K4 (-88.4, 164.9) -> (-65, 188.3)
  line L5 (-77.9, 164.9) -> (-77.9, 154.9)
  curve K5 (-77.9, 164.9) -> (-65, 177.8)
  line L6 (65, 177.8) -> (-65, 177.8)
  curve K6 (65, 177.8) -> (77.9, 164.9)
  line L7 (77.9, 154.9) -> (77.9, 164.9)
  curve K7 (65, 142) -> (77.9, 154.9)
  line L8 (-65, 142) -> (65, 142)
  curve K8 (-77.9, 154.9) -> (-65, 142)
  line L9 (85.9, 164.9) -> (85.9, 154.9)
  curve K9 (65, 185.8) -> (85.9, 164.9)
  line L10 (-65, 185.8) -> (65, 185.8)
  curve K10 (-85.9, 164.9) -> (-65, 185.8)
  line L11 (-85.9, 154.9) -> (-85.9, 164.9)
  curve K11 (-65, 134) -> (-85.9, 154.9)
  line L12 (65, 134) -> (-65, 134)
  curve K12 (85.9, 154.9) -> (65, 134)
  line L13 (-65, 186.3) -> (65, 186.3)
  curve K13 (-86.4, 164.9) -> (-65, 186.3)
  line L14 (-86.4, 154.9) -> (-86.4, 164.9)
  curve K14 (-65, 133.5) -> (-86.4, 154.9)
  line L15 (65, 133.5) -> (-65, 133.5)
  curve K15 (86.4, 154.9) -> (65, 133.5)
  line L16 (86.4, 164.9) -> (86.4, 154.9)
  curve K16 (65, 186.3) -> (86.4, 164.9)
  dimension "d1413" = 0.5
extrude "Estrusione1" add sketch "Schizzo1" profile of L1 K1 L2 K2 L3 K3 L4 K4 L16 L15 K14 L13 K13 L14 K16 K15 along normal blind 10
sketch "Schizzo2" plane through (167, 0, 0) normal (-1, 0, 0) x axis (0, -1, 0)
  line L1 (85.9, 164.9) -> (85.9, 154.9)
  curve K1 (65, 185.8) -> (85.9, 164.9)
  line L2 (-65, 185.8) -> (65, 185.8)
  curve K2 (-85.9, 164.9) -> (-65, 185.8)
  line L3 (-85.9, 154.9) -> (-85.9, 164.9)
  curve K3 (-65, 134) -> (-85.9, 154.9)
  line L4 (65, 134) -> (-65, 134)
  curve K4 (85.9, 154.9) -> (65, 134)
  line L5 (-85.9, 159.9) -> (85.9, 159.9)
  line L6 (0, 134) -> (0, 185.8)
  line L7 (-65, 177.8) -> (65, 177.8)
  curve K5 (65, 177.8) -> (77.9, 164.9)
  curve K6 (-77.9, 164.9) -> (-65, 177.8)
  line L8 (-77.9, 164.9) -> (-77.9, 154.9)
  curve K7 (-77.9, 154.9) -> (-65, 142)
  line L9 (-65, 142) -> (65, 142)
  curve K8 (65, 142) -> (77.9, 154.9)
  line L10 (77.9, 164.9) -> (77.9, 154.9)
  point P10 (85.9, 159.9)
  point P11 (-85.9, 159.9)
  point P12 (0, 185.8)
  point P13 (0, 134)
  point P22 (0, 181.8)
  point P23 (81.9, 159.9)
  point P24 (-81.9, 159.9)
  point P25 (0, 138)
  midpoint L1 P10
  midpoint L3 P11
  midpoint L2 P12
  midpoint L4 P13
  coincident L6 P22
  coincident L5 P23
  symmetric L6 P23 P24
  symmetric L5 P22 P25
  dimension "d1416" distance L7 P22 = 4
  dimension "d1417" distance L10 P23 = 4
hole "Foratura1" HoleDepth 4.8 HoleDiameter 3.5 TipAngle 180
thread "Filettatura1"
sketch "Schizzo3" plane through (167, 0, 0) normal (-1, 0, 0) x axis (0, -1, 0)
  line L1 (85.9, 164.9) -> (85.9, 154.9)
  curve K1 (65, 185.8) -> (85.9, 164.9)
  line L2 (-65, 185.8) -> (65, 185.8)
  curve K2 (-85.9, 164.9) -> (-65, 185.8)
  line L3 (-85.9, 154.9) -> (-85.9, 164.9)
  curve K3 (-65, 134) -> (-85.9, 154.9)
  line L4 (65, 134) -> (-65, 134)
  curve K4 (85.9, 154.9) -> (65, 134)
  curve K5 (86.4, 164.9) -> (65, 186.3)
  line L5 (86.4, 154.9) -> (86.4, 164.9)
  curve K6 (65, 133.5) -> (86.4, 154.9)
  line L6 (-65, 133.5) -> (65, 133.5)
  curve K7 (-86.4, 154.9) -> (-65, 133.5)
  line L7 (-86.4, 164.9) -> (-86.4, 154.9)
  curve K8 (-65, 186.3) -> (-86.4, 164.9)
  line L8 (65, 186.3) -> (-65, 186.3)
  line L9 (-89.2, 154.9) -> (-89.2, 164.9)
  curve K9 (-89.2, 154.9) -> (-65, 130.7)
  line L10 (65, 130.7) -> (-65, 130.7)
  curve K10 (65, 130.7) -> (89.2, 154.9)
  line L11 (89.2, 164.9) -> (89.2, 154.9)
  curve K11 (65, 189.1) -> (89.2, 164.9)
  line L12 (-65, 189.1) -> (65, 189.1)
  curve K12 (-89.2, 164.9) -> (-65, 189.1)
  curve K13 (-85.9, 154.9) -> (-65, 134)
  line L13 (-85.9, 164.9) -> (-85.9, 154.9)
  curve K14 (-65, 185.8) -> (-85.9, 164.9)
  line L14 (65, 185.8) -> (-65, 185.8)
  curve K15 (85.9, 164.9) -> (65, 185.8)
  line L15 (85.9, 154.9) -> (85.9, 164.9)
  curve K16 (65, 134) -> (85.9, 154.9)
  line L16 (-65, 134) -> (65, 134)
  circle C1 centre (-81.9, 159.9) radius 1.75
  circle C2 centre (0, 181.8) radius 1.75
  circle C3 centre (0, 138) radius 1.75
  circle C4 centre (81.9, 159.9) radius 1.75
  dimension "d1424" = 0.5
extrude "Estrusione2" new body sketch "Schizzo3" profile of C1 C2 C3 C4 L1 K1 L2 K2 L3 K3 L4 K4 L14 L13 K13 K15 K14 K16 L15 L16 along normal blind 7
sketch "Schizzo4" plane through (160, 0, 0) normal (-1, 0, 0) x axis (0, -1, 0)
  curve K1 (74.4055, 134.6069) -> (65, 134)
  curve K2 (81.0094, 137.6898) -> (74.4055, 134.6069)
  curve K3 (85.9, 154.9) -> (81.0094, 137.6898)
  line L1 (85.9, 164.9) -> (85.9, 154.9)
  curve K4 (81.0094, 182.1102) -> (85.9, 164.9)
  curve K5 (74.4056, 185.1931) -> (81.0094, 182.1102)
  curve K6 (65, 185.8) -> (74.4056, 185.1931)
  line L2 (-65, 185.8) -> (65, 185.8)
  curve K7 (-78.818, 183.6203) -> (-65, 185.8)
  curve K8 (-81.9485, 181.2032) -> (-78.818, 183.6203)
  curve K9 (-85.9, 164.9) -> (-81.9485, 181.2032)
  line L3 (-85.9, 154.9) -> (-85.9, 164.9)
  curve K10 (-81.9485, 138.5968) -> (-85.9, 154.9)
  curve K11 (-78.818, 136.1797) -> (-81.9485, 138.5968)
  curve K12 (-65, 134) -> (-78.818, 136.1797)
  line L4 (65, 134) -> (-65, 134)
  curve K13 (-79.0124, 178.4868) -> (-76.9033, 180.1084)
  curve K14 (-81.9, 164.9) -> (-79.0124, 178.4868)
  line L5 (-81.9, 154.9) -> (-81.9, 164.9)
  curve K15 (-79.0124, 141.3132) -> (-81.9, 154.9)
  curve K16 (-76.9033, 139.6916) -> (-79.0124, 141.3132)
  curve K17 (-65, 138) -> (-76.9033, 139.6916)
  line L6 (65, 138) -> (-65, 138)
  curve K18 (73.5898, 138.5229) -> (65, 138)
  curve K19 (78.3954, 140.7174) -> (73.5898, 138.5229)
  curve K20 (81.9, 154.9) -> (78.3954, 140.7174)
  line L7 (81.9, 164.9) -> (81.9, 154.9)
  curve K21 (78.3954, 179.0826) -> (81.9, 164.9)
  curve K22 (73.5898, 181.2771) -> (78.3954, 179.0826)
  curve K23 (65, 181.8) -> (73.5898, 181.2771)
  line L8 (-65, 181.8) -> (65, 181.8)
  curve K24 (-76.9033, 180.1084) -> (-65, 181.8)
  circle C1 centre (0, 181.8) radius 1.75
  circle C2 centre (0, 138) radius 1.75
  circle C3 centre (81.9, 159.9) radius 1.75
  circle C4 centre (-81.9, 159.9) radius 1.75
  circle C5 centre (81.9, 159.9) radius 3
  circle C6 centre (0, 181.8) radius 3
  circle C7 centre (0, 138) radius 3
  circle C8 centre (-81.9, 159.9) radius 3
  concentric C3 C5
  concentric C1 C6
  concentric C2 C7
  concentric C4 C8
  dimension "d1427" = -4
  dimension "d1428" diameter C5 = 6
  dimension "d1429" diameter C6 = 6
  dimension "d1430" diameter C7 = 6
  dimension "d1431" diameter C8 = 6
extrude "Estrusione3" cut sketch "Schizzo4" profile of K18 K13 K14 L5 K15 K16 L6 K17 K19 K20 L7 K21 K22 K23 L8 K24 C5 C6 C7 C8 against normal blind 7
component_from_bodies "Corpo->Comp1"
sketch "Schizzo5" plane through (0, 0, 0) normal (1, 0, 0) x axis (0, 1, 0)
copy_paste "TagliaIncolla3"
sketch "Schizzo6" plane through (0, 0, -230.3) normal (0, 0, -1) x axis (1, 0, 0)
  line L1 (95, -64.5) -> (-95, -64.5)
  curve K1 (95, -64.5) -> (134.5, -25)
  line L2 (134.5, 25) -> (134.5, -25)
  curve K2 (95, 64.5) -> (134.5, 25)
  line L3 (-95, 64.5) -> (95, 64.5)
  curve K3 (-95, 64.5) -> (-134.5, 25)
  line L4 (-134.5, -25) -> (-134.5, 25)
  curve K4 (-95, -64.5) -> (-134.5, -25)
  circle C1 centre (-47.5, 60) radius 1.75
  circle C2 centre (-130, 25) radius 1.75
  circle C3 centre (-95, 60) radius 1.75
  circle C4 centre (-95, -60) radius 1.75
  circle C5 centre (-130, -25) radius 1.75
  circle C6 centre (-47.5, -60) radius 1.75
  circle C7 centre (47.5, -60) radius 1.75
  circle C8 centre (130, -25) radius 1.75
  circle C9 centre (95, -60) radius 1.75
  circle C10 centre (95, 60) radius 1.75
  circle C11 centre (130, 25) radius 1.75
  circle C12 centre (47.5, 60) radius 1.75
  circle C13 centre (95, -60) radius 1.75
  circle C14 centre (95, 60) radius 1.75
  circle C15 centre (-95, -60) radius 1.75
  circle C16 centre (-95, 60) radius 1.75
extrude "Estrusione3" add sketch "Schizzo6" profile of C3 C6 C9 C10 C13 C14 C16 against normal blind 3
remove_instance "RimuoviIstanza2"
component_insert "Inserimento componente1"
sketch "Schizzo5" plane through (170, 0, 0) normal (1, 0, 0) x axis (0, 1, 0)
  line L1 (-85.9, 154.9) -> (-85.9, 164.9)
  curve K1 (-65, 134) -> (-85.9, 154.9)
  line L2 (65, 134) -> (-65, 134)
  curve K2 (85.9, 154.9) -> (65, 134)
  line L3 (85.9, 164.9) -> (85.9, 154.9)
  curve K3 (85.9, 164.9) -> (65, 185.8)
  line L4 (-65, 185.8) -> (65, 185.8)
  curve K4 (-65, 185.8) -> (-85.9, 164.9)
  line L5 (77.9, 164.9) -> (77.9, 154.9)
  line L6 (65, 177.8) -> (-65, 177.8)
  line L7 (65, 142) -> (-65, 142)
  line L8 (21.5753, 159.9) -> (77.9, 159.9)
  circle C1 centre (81.9, 159.9) radius 1.75
  circle C2 centre (0, 181.8) radius 1.75
  circle C3 centre (0, 138) radius 1.75
  circle C4 centre (-81.9, 159.9) radius 1.75
  circle C5 centre (60, 159.9) radius 3.5
  point P21 (77.9, 159.9)
  point P20 (60, 159.9)
  midpoint L5 P21
  perpendicular L5 L8
  coincident P20 L8
  dimension "d1468" diameter C5 = 7
  dimension "d1469" distance L6 P20 = 17.9
  dimension "d1470" distance P20 P21 = 17.9
extrude "Estrusione2" cut sketch "Schizzo5" profile of C5 against normal blind 3
joint "Assembla1" alignAngle -90 alignOffsetX 0 alignOffsetY 0 alignOffsetZ 0
work_plane "Piano di lavoro2" AlongDistance -12
work_plane "Piano di lavoro1" AlongDistance 6
sketch "Schizzo1" plane through (176, 0, 0) normal (1, 0, 0) x axis (0, 1, 0)
  line L1 (42.1, 142) -> (42.1, 177.8)
  line L2 (77.9, 142) -> (42.1, 142)
  line L3 (77.9, 177.8) -> (77.9, 142)
  line L4 (42.1, 177.8) -> (77.9, 177.8)
  curve K1 (77.9, 164.9) -> (65, 177.8)
  line L5 (60, 177.8) -> (60, 159.9)
  curve K2 (55, 177.8) -> (42.1, 164.9)
  curve K3 (42.1, 154.9) -> (55, 142)
  curve K4 (65, 142) -> (77.9, 154.9)
  circle C1 centre (60, 159.9) radius 3.5
  circle C2 centre (60, 159.9) radius 3.05
  circle C3 centre (60, 159.9) radius 25.3144
  point P3 (60, 159.9)
  point P9 (60, 159.9)
  point P5 (42.1, 177.8)
  point P11 (77.9, 164.9)
  point P12 (60, 159.9)
  point P13 (60, 177.8)
  point P10 (65, 177.8)
  concentric C1 C2
  concentric C2 C3
  coincident P3 P9
  coincident C3 P5
  horizontal L4
  coincident L3 P11
  coincident P9 P12
  midpoint L4 P13
  dimension "d1479" diameter C2 = 6.1
  dimension "d1481" distance L4 P10 = 0
  dimension "d1483" C-Pattern1-Angle = 360
extrude "Estrusione1" new body sketch "Schizzo1" profile of C2 L1 L2 L3 L4 K1 K2 K3 K4 along normal blind 15
work_plane "Piano di lavoro2"
sketch "Schizzo2" plane through (0, 60, 0) normal (0, -1, 0) x axis (-1, 0, 0)
  line L1 (-191, -156.85) -> (-191, -162.95)
  line L2 (-191, -164.9) -> (-191, -177.8)
  line L3 (-191, -154.9) -> (-191, -164.9)
  line L4 (-191, -142) -> (-191, -154.9)
  line L5 (-191, -154.9) -> (-191, -142)
  line L6 (-191, -164.9) -> (-191, -154.9)
  line L7 (-191, -177.8) -> (-191, -164.9)
  line L8 (-191, -177.8) -> (-176, -177.8)
  line L9 (-176, -177.8) -> (-191, -177.8)
  line L10 (-176, -156.85) -> (-176, -162.95)
  line L11 (-176, -164.9) -> (-176, -177.8)
  line L12 (-176, -154.9) -> (-176, -164.9)
  line L13 (-176, -142) -> (-176, -154.9)
  line L14 (-176, -154.9) -> (-176, -142)
  line L15 (-176, -164.9) -> (-176, -154.9)
  line L16 (-176, -177.8) -> (-176, -164.9)
  curve K1 (-187, -177.8) -> (-191, -177.8)
  curve K2 (-183.5, -176.3) -> (-187, -177.8)
  curve K3 (-180, -174.8) -> (-183.5, -176.3)
  curve K4 (-176, -174.8) -> (-180, -174.8)
  curve K5 (-176, -174.8) -> (-191, -177.8)
  point P16 (-187, -177.8)
  point P19 (-176, -174.8)
  point P4 (-191, -177.8)
  point P18 (-180, -174.8)
  point P8 (-176, -177.8)
  coincident L9 P16
  horizontal K4
  parallel K2 K3
  equal K2 K3
  coincident L11 P19
  dimension "d1486" distance P4 P16 = 4
  dimension "d1487" distance P18 P19 = 4
  dimension "d1488" distance P8 P19 = 3
sketch "Schizzo3" plane through (191, 0, 0) normal (1, 0, 0) x axis (0, 1, 0)
  line L1 (55, 177.8) -> (65, 177.8)
  curve K1 (42.1, 164.9) -> (55, 177.8)
  line L2 (42.1, 154.9) -> (42.1, 164.9)
  curve K2 (55, 142) -> (42.1, 154.9)
  line L3 (65, 142) -> (55, 142)
  curve K3 (77.9, 154.9) -> (65, 142)
  line L4 (77.9, 164.9) -> (77.9, 154.9)
  curve K4 (65, 177.8) -> (77.9, 164.9)
  line L5 (60, 142) -> (60, 177.8)
  circle C1 centre (60, 159.9) radius 3.05
  point P11 (60, 177.8)
  point P12 (60, 142)
  midpoint L1 P11
  midpoint L3 P12
sweep "Sweep1" sketch "Schizzo2" TwistAngle 0 TaperAngle 0
fillet "Raccordo1" radius 3
sketch "Schizzo4" plane through (191, 0, 0) normal (1, 0, 0) x axis (0, 1, 0)
  curve K1 (45.4544, 154.9) -> (55, 145.3544)
  line L1 (55, 145.3544) -> (65, 145.3544)
  curve K2 (65, 145.3544) -> (74.5456, 154.9)
  line L2 (74.5456, 154.9) -> (74.5456, 164.9)
  curve K3 (74.5456, 164.9) -> (65, 174.4456)
  line L3 (65, 174.4456) -> (55, 174.4456)
  curve K4 (55, 174.4456) -> (45.4544, 164.9)
  line L4 (45.4544, 164.9) -> (45.4544, 154.9)
  line L5 (57.3213, 160.4292) -> (61.5754, 162.1302)
  circle C1 centre (60, 159.9) radius 3.05
  arc A1 centre (60, 159.9) radius 2.7305 clockwise from (61.5754, 162.1302) to (57.3213, 160.4292)
  point P2 (60, 159.9)
  dimension "d1499" distance P2 L5 = 1.4859
extrude "Estrusione3" add sketch "Schizzo4" profile of C1 A1 L5 to an object
sketch "Schizzo5" plane through (176, 0, 0) normal (-1, 0, 0) x axis (0, -1, 0)
  curve K1 (-74.9, 164.9) -> (-65, 174.8)
  line L1 (-74.9, 154.9) -> (-74.9, 164.9)
  curve K2 (-65, 145) -> (-74.9, 154.9)
  line L2 (-55, 145) -> (-65, 145)
  curve K3 (-45.1, 154.9) -> (-55, 145)
  line L3 (-45.1, 164.9) -> (-45.1, 154.9)
  curve K4 (-55, 174.8) -> (-45.1, 164.9)
  line L4 (-65, 174.8) -> (-55, 174.8)
  line L5 (-62.4622, 161.7) -> (-57.5378, 161.7)
  circle C1 centre (-60, 159.9) radius 3.05
  circle C2 centre (-60, 159.9) radius 3.05
  point P12 (-57.5378, 161.7)
  point P13 (-62.4622, 161.7)
  point P11 (-60, 159.9)
  coincident C1 P12
  coincident C1 P13
  horizontal L5
  dimension "d1502" distance P11 L5 = 1.8
extrude "Estrusione4" add sketch "Schizzo5" profile of C1 C2 L5 to an object
chamfer "Smusso1" distance 1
